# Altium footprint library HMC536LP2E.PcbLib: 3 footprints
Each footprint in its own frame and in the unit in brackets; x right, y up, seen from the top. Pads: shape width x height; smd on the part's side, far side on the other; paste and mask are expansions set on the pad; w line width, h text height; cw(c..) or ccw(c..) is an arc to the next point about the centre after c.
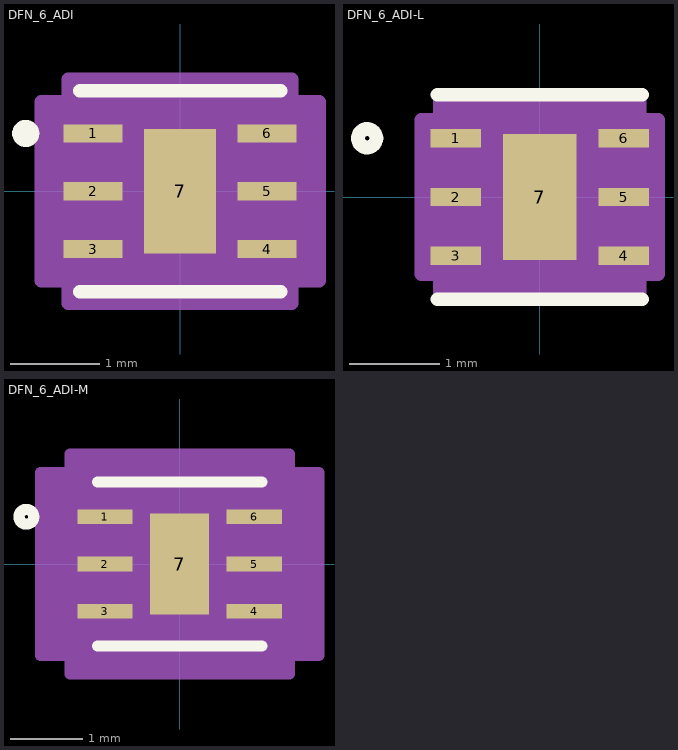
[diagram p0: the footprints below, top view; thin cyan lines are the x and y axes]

## DFN_6_ADI [mil]
pads (7):
  rect 26x8 smd paste+0 mask+0: 1(-38.5,25.59) 2(-38.5,0) 3(-38.5,-25.59) 4(38.5,-25.59) 5(38.5,0) 6(38.5,25.59)
  rect 32x55 smd paste+0 mask+0: 7(0,0)
Top Overlay:
  circle w6: c-68.3,25.59 r3
  lines w6: -44.5,-44.5 44.5,-44.5 ; -44.5,44.5 44.5,44.5
Mechanical 13:
  circle w6: c-25.5,25.59 r0
  lines w0: -12,39.5 ccw(c0,39.5) 12,39.5
  lines w1: -39.5,-39.5 39.5,-39.5 39.5,39.5 -39.5,39.5 -39.5,-39.5
Mechanical 15:
  region: -49.5,-39.59 -61.5,-39.59 -61.5,39.59 -49.5,39.59 -49.5,49.5 49.5,49.5 49.5,39.59 61.5,39.59 61.5,-39.59 49.5,-39.59 49.5,-49.5 -49.5,-49.5
  lines w6: -61.5,-39.59 -61.5,39.59 -49.5,39.59 -49.5,49.5 49.5,49.5 49.5,39.59 61.5,39.59 61.5,-39.59 49.5,-39.59 49.5,-49.5 -49.5,-49.5 -49.5,-39.59 -61.5,-39.59
3D body "DFN_6_ADI.step": height 39.09, standoff 0, extent -39.49,-39.49 39.49,39.49

## DFN_6_ADI-L [mil]
pads (7):
  rect 22x8 smd paste+0 mask+0: 1(-36.5,25.59) 2(-36.5,0) 3(-36.5,-25.59) 4(36.5,-25.59) 5(36.5,0) 6(36.5,25.59)
  rect 32x55 smd paste+0 mask+0: 7(0,0)
Top Overlay:
  circle w6: c-75.09,25.59 r4
  lines w6: -44.5,-44.5 44.5,-44.5 ; -44.5,44.5 44.5,44.5
Mechanical 13:
  circle w0: c-25.5,25.59 r3
  lines w0: -12,39.5 ccw(c0,39.5) 12,39.5
  lines w1: -39.5,-39.5 39.5,-39.5 39.5,39.5 -39.5,39.5 -39.5,-39.5
Mechanical 15:
  region: -43.5,-33.59 -51.5,-33.59 -51.5,33.59 -43.5,33.59 -43.5,43.5 43.5,43.5 43.5,33.59 51.5,33.59 51.5,-33.59 43.5,-33.59 43.5,-43.5 -43.5,-43.5
  lines w6: -51.5,-33.59 -51.5,33.59 -43.5,33.59 -43.5,43.5 43.5,43.5 43.5,33.59 51.5,33.59 51.5,-33.59 43.5,-33.59 43.5,-43.5 -43.5,-43.5 -43.5,-33.59 -51.5,-33.59
3D body "DFN_6_ADI.step": height 39.09, standoff 0, extent -39.49,-39.49 39.49,39.49

## DFN_6_ADI-M [mil]
pads (7):
  rect 30x8 smd paste+0 mask+0: 1(-40.5,25.59) 2(-40.5,0) 3(-40.5,-25.59) 4(40.5,-25.59) 5(40.5,0) 6(40.5,25.59)
  rect 32x55 smd paste+0 mask+0: 7(0,0)
Top Overlay:
  circle w6: c-83.09,25.59 r4
  lines w6: -44.5,-44.5 44.5,-44.5 ; -44.5,44.5 44.5,44.5
Mechanical 13:
  circle w0: c-25.5,25.59 r3
  lines w0: -12,39.5 ccw(c0,39.5) 12,39.5
  lines w1: -39.5,-39.5 39.5,-39.5 39.5,39.5 -39.5,39.5 -39.5,-39.5
Mechanical 15:
  region: -59.5,-49.59 -75.5,-49.59 -75.5,49.59 -59.5,49.59 -59.5,59.5 59.5,59.5 59.5,49.59 75.5,49.59 75.5,-49.59 59.5,-49.59 59.5,-59.5 -59.5,-59.5
  lines w6: -75.5,-49.59 -75.5,49.59 -59.5,49.59 -59.5,59.5 59.5,59.5 59.5,49.59 75.5,49.59 75.5,-49.59 59.5,-49.59 59.5,-59.5 -59.5,-59.5 -59.5,-49.59 -75.5,-49.59
3D body "DFN_6_ADI.step": height 39.09, standoff 0, extent -39.49,-39.49 39.49,39.49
